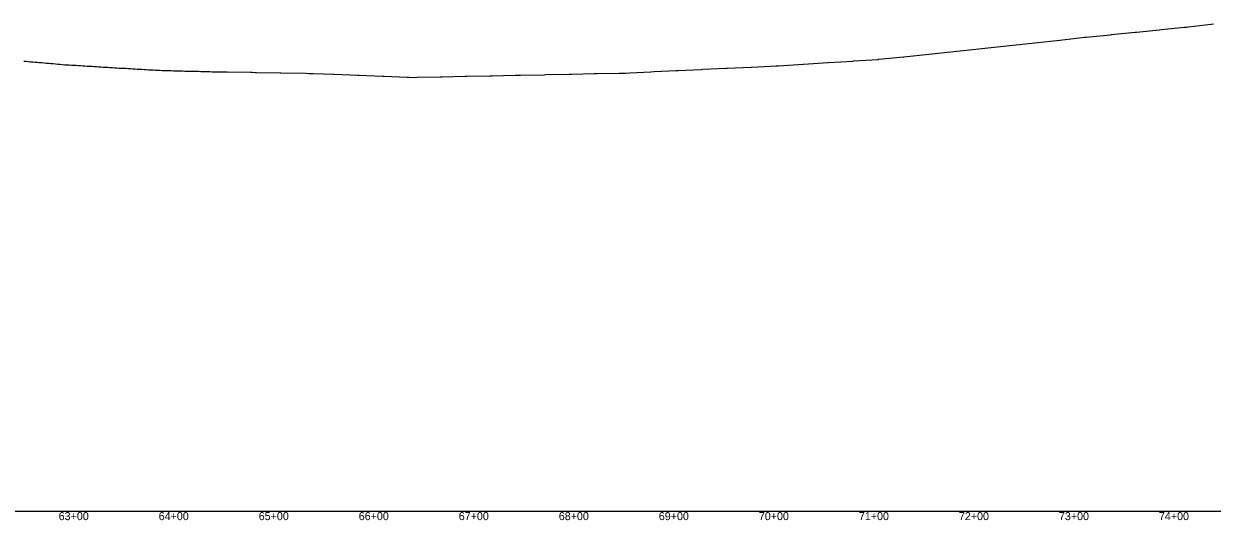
# Model space of a CAD drawing. Extents: x 49922 to 54713, y 49991 to 62800.
# Drawn here: x 52247 to 53436, y 49991 to 50488 of the extents above; entities that cross this region are included whole.
import ezdxf

# ---------------------------------------------------------------- set-up
doc = ezdxf.new("R2010")
doc.units = 0
for name, color, linetype in [('RD_DDB_Profile_EX', 7, 'Continuous'), ('RD_DDB_StaTX', 7, 'Continuous'), ('RD_GPK_Profile_Cell', 7, 'Continuous')]:
    doc.layers.add(name, color=color, linetype=linetype)

msp = doc.modelspace()

# ---------------------------------------------------------------- linework, layer by layer
at = {"layer": 'RD_DDB_Profile_EX'}
for points in [[(52817.6, 50437.8), (52820.9, 50437.8), (52842.6, 50438.3), (52843.6, 50438.3), (52849.5, 50438.4), (52853.4, 50438.6), (52874.5, 50439.6), (52877.8, 50439.8), (52899.6, 50440.8), (52902.1, 50440.9), (52924.6, 50442), (52926.4, 50442.1), (52949.6, 50443.2), (52950.7, 50443.2), (52974.7, 50444.4), (52975, 50444.4), (52987.6, 50445), (52999.4, 50445.5), (52999.7, 50445.5), (53002, 50445.6), (53026.6, 50447.2), (53027, 50447.2), (53051.6, 50448.8), (53052, 50448.8), (53076.6, 50450.4), (53077, 50450.5), (53101.6, 50452), (53102, 50452.1), (53102.5, 50452.1), (53127.1, 50454.7), (53127.5, 50454.7), (53152.2, 50457.3), (53152.5, 50457.3), (53177.5, 50459.9), (53202.5, 50462.5), (53208.2, 50463.1), (53233.2, 50465.9), (53258.2, 50468.6), (53283.2, 50471.4), (53308.1, 50474.1), (53309.8, 50474.3), (53334.1, 50476.7), (53334.9, 50476.8), (53358.6, 50479.2), (53359.9, 50479.3), (53383, 50481.7), (53384.9, 50481.9), (53407.5, 50484.1), (53410, 50484.4), (53411.8, 50484.6), (53434.6, 50487.4), (53436.8, 50487.7)], [(52247.4, 50450.2), (52249.7, 50450.1), (52252, 50449.9), (52254.2, 50449.7), (52256.5, 50449.5), (52258.8, 50449.4), (52261, 50449.2), (52262.8, 50449), (52263.3, 50449), (52265.6, 50448.8), (52267.9, 50448.5), (52270.1, 50448.4), (52272.4, 50448.2), (52274.7, 50448), (52276.9, 50447.8), (52279.2, 50447.6), (52281.5, 50447.4), (52283.7, 50447.2), (52286, 50447), (52288.5, 50446.7), (52290.6, 50446.6), (52292.8, 50446.5), (52295.1, 50446.4), (52297.4, 50446.3), (52299.6, 50446.1), (52301.9, 50446), (52304.2, 50445.8), (52306.4, 50445.7)], [(52306.4, 50445.7), (52308.7, 50445.6), (52311, 50445.4), (52312.1, 50445.4), (52313.5, 50445.3), (52315.5, 50445.1), (52317.8, 50445), (52320.1, 50444.8), (52322.3, 50444.7), (52324.6, 50444.5), (52326.9, 50444.4), (52329.2, 50444.2), (52331.4, 50444.1), (52333.4, 50443.9), (52333.7, 50443.9), (52336, 50443.8), (52338.2, 50443.7), (52340.5, 50443.6), (52342.8, 50443.4), (52345, 50443.3), (52347.3, 50443.2), (52349.6, 50443.1), (52351.9, 50442.9), (52354.1, 50442.8), (52356.4, 50442.7), (52358.3, 50442.6), (52358.7, 50442.5), (52360.9, 50442.4), (52361.3, 50442.3), (52363.2, 50442.2), (52365.5, 50442.1), (52367.7, 50442), (52370, 50441.8), (52372.3, 50441.7), (52374.6, 50441.6), (52376.8, 50441.5), (52379.3, 50441.3), (52381.4, 50441.2), (52383.6, 50441.1), (52385.9, 50441), (52388.2, 50441), (52390.5, 50440.9), (52392.7, 50440.8), (52395, 50440.8), (52397.3, 50440.7), (52399.5, 50440.6), (52401.8, 50440.6), (52404.3, 50440.5), (52406.3, 50440.5), (52408.6, 50440.4), (52410.9, 50440.3), (52413.2, 50440.3), (52415.4, 50440.2), (52417.7, 50440.2), (52420, 50440.1), (52422.2, 50440.1), (52424.5, 50440), (52425.8, 50439.9), (52426.8, 50439.9), (52429.1, 50439.8), (52431.3, 50439.8), (52433.6, 50439.8), (52435.9, 50439.7), (52438.1, 50439.7), (52440.4, 50439.7), (52447.7, 50439.5), (52450.7, 50439.5), (52474.3, 50439.1), (52475.9, 50439.1), (52479.2, 50439), (52480.3, 50439), (52504.2, 50438.5), (52504.8, 50438.5), (52529.3, 50438.1), (52532.9, 50438), (52536.7, 50437.9), (52557.3, 50437.1), (52557.8, 50437.1), (52581.8, 50436.1), (52582.8, 50436.1), (52606.2, 50435.2), (52607.8, 50435.2), (52630.7, 50434.3), (52632.8, 50434.2), (52633.2, 50434.2), (52638.6, 50434), (52640.9, 50434.1), (52663.7, 50434.5), (52665.7, 50434.6), (52688.7, 50435.1), (52690.5, 50435.1), (52713.7, 50435.6), (52715.3, 50435.6), (52738.9, 50436.1), (52742.7, 50436.2), (52744, 50436.2), (52767.7, 50436.7), (52769.6, 50436.8), (52792.7, 50437.2), (52795.3, 50437.3), (52817.6, 50437.8)]]:
    msp.add_lwpolyline(points, dxfattribs=at)
at = {"layer": 'RD_GPK_Profile_Cell'}
msp.add_line((50000, 50000), (54600, 50000), dxfattribs=at)

# ---------------------------------------------------------------- texts
at = {"layer": 'RD_DDB_StaTX'}
for s, p in [('63+00', (52282.4, 49991)), ('64+00', (52382.4, 49991)), ('65+00', (52482.4, 49991)), ('66+00', (52582.4, 49991)), ('67+00', (52682.4, 49991)), ('68+00', (52782.4, 49991)), ('69+00', (52882.4, 49991)), ('70+00', (52982.4, 49991)), ('71+00', (53082.4, 49991)), ('72+00', (53182.4, 49991)), ('73+00', (53282.4, 49991)), ('74+00', (53382.4, 49991))]:
    msp.add_text(s, height=8, dxfattribs=at).set_placement(p)

doc.saveas('drawing.dxf')
